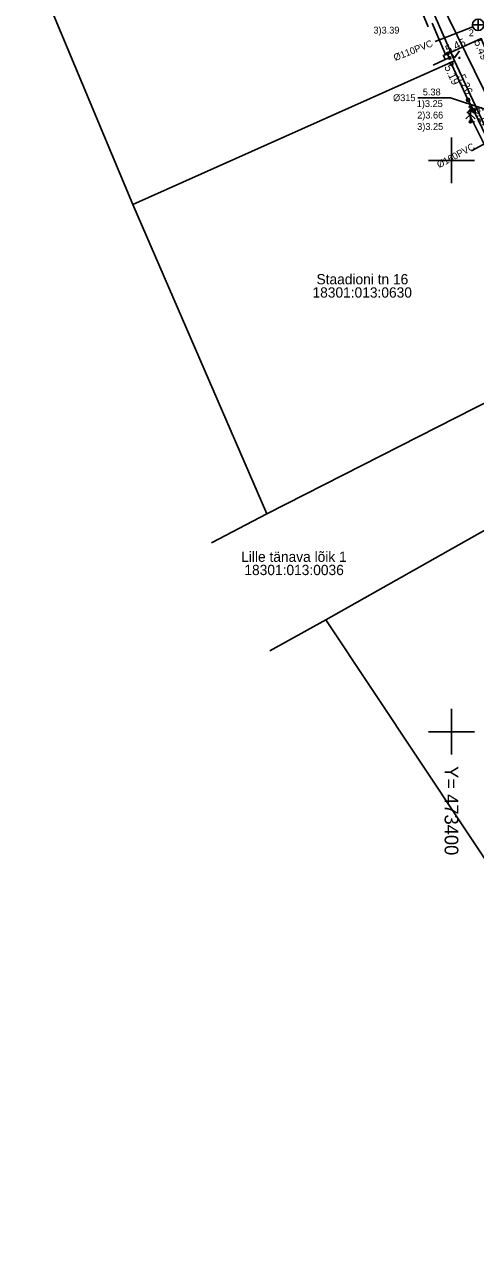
# Model space of a CAD drawing. Extents: x 473307 to 473719, y 6532843 to 6533381.
# Drawn here: x 473362.6 to 473402.1, y 6533004.9 to 6533111.9 of the extents above; entities that cross this region are included whole.
import ezdxf

# ---------------------------------------------------------------- set-up
doc = ezdxf.new("R2010")
doc.units = 0
for name, color, linetype in [('AED', 7, 'Continuous'), ('Default', 7, 'Continuous'), ('HALJASTUS', 7, 'Continuous'), ('KKAEV', 7, 'Continuous'), ('KKAEV_NR', 7, 'Continuous'), ('KORGUS', 7, 'Continuous'), ('KTRASS', 7, 'Continuous'), ('KTRASS_TEKST', 7, 'Continuous'), ('PIIR', 7, 'Continuous'), ('PUU', 7, 'Continuous'), ('SITRASS', 7, 'Continuous'), ('TEE', 7, 'Continuous'), ('VORK', 7, 'Continuous')]:
    doc.layers.add(name, color=color, linetype=linetype)

# ---------------------------------------------------------------- blocks, each defined once
blk = doc.blocks.new('KUUSK1')
at = {"layer": 'Default'}
for p, q in [((0, 2.2), (-0.6, 1.5)), ((0, 3), (-0.3, 2.5)), ((0.3, 2.5), (0, 3)), ((0, 3), (0, 0)), ((0.6, 1.5), (0, 2.2)), ((0, 1.3), (-0.8, 0.5)), ((0.8, 0.5), (0, 1.3)), ((0.72, 0), (0, 0))]:
    blk.add_line(p, q, dxfattribs=at)
blk = doc.blocks.new('KAKAEV')
at = {"layer": 'Default'}
for p, q in [((-1, 0), (1, 0)), ((0, -1), (0, 1))]:
    blk.add_line(p, q, dxfattribs=at)
blk.add_circle((0, 0), 1, dxfattribs=at)
blk = doc.blocks.new('VARPOS')
at = {"layer": 'Default'}
for p, q in [((-0.25, 0.25), (-0.25, -0.25)), ((-0.25, 0.25), (0.25, 0.25)), ((0.25, 0.25), (0.25, -0.25)), ((-0.25, -0.25), (0.25, -0.25))]:
    blk.add_line(p, q, dxfattribs=at)
blk = doc.blocks.new('MURU')
at = {"layer": 'Default'}
for p, q in [((-0.93, 1.21), (0, 0)), ((0, 0), (0.89, 1.21))]:
    blk.add_line(p, q, dxfattribs=at)
for centre in [(-0.8, 0), (0.86, 0)]:
    blk.add_circle(centre, 0.11, dxfattribs=at)
blk = doc.blocks.new('VKORIS')
at = {"layer": 'Default'}
for p, q in [((0, 4), (0, -4)), ((-4, 0), (4, 0))]:
    blk.add_line(p, q, dxfattribs=at)

msp = doc.modelspace()

# ---------------------------------------------------------------- linework, layer by layer
at = {"layer": 'AED'}
for points in [[(473398.31, 6533112.01), (473399.47, 6533109.26)], [(473399.44, 6533108.81), (473398.39, 6533108.32)], [(473399.66, 6533109.33), (473399.81, 6533108.96), (473399.44, 6533108.81), (473399.29, 6533109.18), (473399.66, 6533109.33)], [(473400.04, 6533108.35), (473401.4, 6533105.39)], [(473401.51, 6533105.16), (473401.86, 6533104.5)], [(473409.83, 6533082.93), (473411.7, 6533083.92), (473404.05, 6533099.95), (473401.97, 6533104.27)]]:
    msp.add_lwpolyline(points, dxfattribs=at)
at = {"layer": 'HALJASTUS'}
for points in [[(473397.96, 6533111.68), (473394.6, 6533119.78)], [(473411.46, 6533083.71), (473403.69, 6533099.77), (473401.5, 6533104.16)]]:
    msp.add_lwpolyline(points, dxfattribs=at)
at = {"layer": 'KKAEV_NR'}
msp.add_lwpolyline([(473405.76, 6533103.55), (473399.91, 6533105.48), (473397.06, 6533105.48)], dxfattribs=at)
at = {"layer": 'KORGUS'}
for centre in [(473399.66, 6533109.33), (473399.83, 6533108.96), (473399.99, 6533108.46), (473401.45, 6533105.28), (473401.98, 6533104.44), (473401.66, 6533103.37)]:
    msp.add_circle(centre, 0.1, dxfattribs=at)
at = {"layer": 'KTRASS'}
for points in [[(473398.58, 6533110.39), (473401.86, 6533111.68)], [(473401.76, 6533100.84), (473403.42, 6533101.74), (473405.8, 6533103.14)]]:
    msp.add_lwpolyline(points, dxfattribs=at)
at = {"layer": 'PIIR'}
for points in [[(473492.55, 6532977.62), (473473.12, 6532997.79), (473458.1, 6533015.44), (473444.45, 6533033.74), (473430.52, 6533052.35), (473416.35, 6533075.22), (473412.06, 6533083.41), (473400.27, 6533108.71), (473390.77, 6533130.51), (473383.02, 6533152.56), (473376.06, 6533174.78), (473369.76, 6533197.52)], [(473379, 6533066.53), (473383.85, 6533069.06), (473412.06, 6533083.41), (473416.35, 6533075.22), (473389.01, 6533059.81), (473384.12, 6533057.09)]]:
    msp.add_lwpolyline(points, dxfattribs=at)
for points in [[(473362.64, 6533118.82), (473390.77, 6533130.51), (473400.27, 6533108.71), (473372.12, 6533096.13)], [(473372.12, 6533096.13), (473400.27, 6533108.71), (473412.06, 6533083.41), (473383.85, 6533069.06)], [(473389.01, 6533059.81), (473416.35, 6533075.22), (473430.52, 6533052.35), (473405.34, 6533035.25)]]:
    msp.add_lwpolyline(points, close=True, dxfattribs=at)
at = {"layer": 'SITRASS'}
msp.add_lwpolyline([(473373.61, 6533188.36), (473382.33, 6533159.31), (473384.49, 6533152.12), (473388.46, 6533141.59), (473398.2, 6533115.64), (473410.45, 6533090.65)], dxfattribs=at)
at = {"layer": 'TEE'}
msp.add_lwpolyline([(473416.97, 6533088.93), (473412.68, 6533098.08), (473407.87, 6533107.18), (473404.84, 6533105.6), (473403.55, 6533108.31), (473402.6, 6533110.66), (473399.66, 6533109.33)], dxfattribs=at)

# ---------------------------------------------------------------- block references
at = {"layer": 'AED'}
for p, xscale, yscale, rotation in [((473399.99, 6533108.46), 0.5000000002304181, 0.5, 115.55650486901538), ((473401.45, 6533105.28), 0.5000000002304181, 0.5, 115.55650486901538), ((473401.91, 6533104.38), 0.4999999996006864, 0.5000000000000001, 114.92733221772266)]:
    msp.add_blockref('VARPOS', p, dxfattribs=dict(at, xscale=xscale, yscale=yscale, rotation=rotation))
at = {"layer": 'HALJASTUS', "xscale": 0.5, "yscale": 0.5}
msp.add_blockref('MURU', (473400.27, 6533108.97), dxfattribs=at)
at = {"layer": 'KKAEV', "xscale": 0.5, "yscale": 0.5}
msp.add_blockref('KAKAEV', (473402.33, 6533111.86), dxfattribs=at)
at = {"layer": 'PUU', "xscale": 0.5, "yscale": 0.5}
msp.add_blockref('KUUSK1', (473401.66, 6533103.37), dxfattribs=at)
at = {"layer": 'VORK', "xscale": 0.5, "yscale": 0.5}
for p in [(473400, 6533100), (473400, 6533050)]:
    msp.add_blockref('VKORIS', p, dxfattribs=at)

# ---------------------------------------------------------------- texts
at = {"layer": 'KKAEV_NR'}
for s, p in [('3)3.39', (473393.17, 6533111.09)), ('2', (473401.51, 6533110.86)), ('%%c315', (473394.89, 6533105.18)), ('5.38', (473397.49, 6533105.68)), ('1)3.25', (473396.96, 6533104.66)), ('2)3.66', (473397, 6533103.66)), ('3)3.25', (473397, 6533102.66))]:
    msp.add_text(s, height=0.6, dxfattribs=at).set_placement(p)
at = {"layer": 'KORGUS'}
for s, rotation, p in [('5.45', 24.2115, (473399.66, 6533109.33)), ('5.49', 292.0878, (473401.95, 6533110.39)), ('5.19', 294.6724, (473399.35, 6533108.17)), ('5.26', 294.6724, (473400.51, 6533107.34)), ('5.17', 296.6084, (473401.98, 6533104.44))]:
    msp.add_text(s, height=0.7, rotation=rotation, dxfattribs=at).set_placement(p)
at = {"layer": 'KTRASS_TEKST'}
for s, rotation, p in [('%%c110PVC', 21.5059, (473395.07, 6533108.68)), ('%%c160PVC', 28.4164, (473398.92, 6533099.3))]:
    msp.add_text(s, height=0.6, rotation=rotation, dxfattribs=at).set_placement(p)
at = {"layer": 'PIIR'}
for s, p in [('Staadioni tn 16', (473388.19, 6533089.15)), ('18301:013:0630', (473387.84, 6533087.99)), ('Lille tänava lõik 1', (473381.6, 6533064.87)), ('18301:013:0036', (473381.88, 6533063.71))]:
    msp.add_text(s, height=0.9, dxfattribs=at).set_placement(p)
at = {"layer": 'VORK'}
msp.add_text('Y= 473400', height=1.2, rotation=270, dxfattribs=at).set_placement((473399.4, 6533047))

doc.saveas('drawing.dxf')
